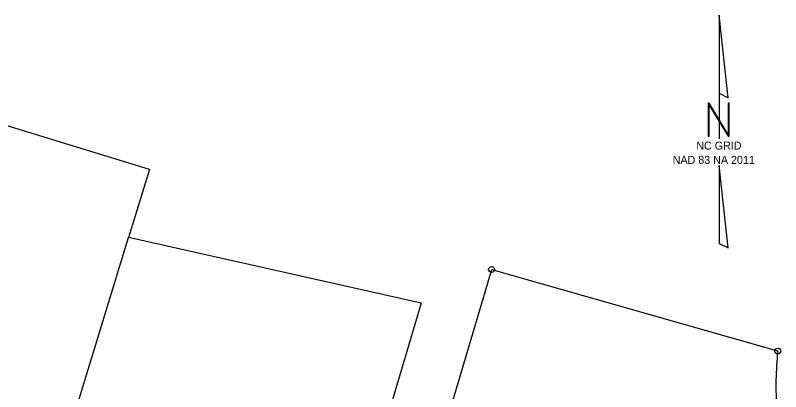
# Model space of a CAD drawing. Extents: x 2110969 to 2113691, y 670003 to 672285.
# Drawn here: x 2112129 to 2112703, y 670669 to 670951 of the extents above; entities that cross this region are included whole.
import ezdxf

# ---------------------------------------------------------------- set-up
doc = ezdxf.new("R2010")
doc.units = 0
for name, color, linetype in [('CTL North Arrow NAD 83 NA 2011 CELL', 7, 'Continuous'), ('Exist Property Iron Pin CELL', 7, 'Continuous'), ('Exist Property Line', 7, 'Continuous'), ('Exist Right of Way Line', 7, 'Continuous')]:
    doc.layers.add(name, color=color, linetype=linetype)

msp = doc.modelspace()

# ---------------------------------------------------------------- linework, layer by layer
at = {"layer": 'CTL North Arrow NAD 83 NA 2011 CELL'}
msp.add_line((2112657.28, 670863.37), (2112657.28, 670863.37), dxfattribs=at)
for points in [[(2112657.13, 670950.66), (2112657.13, 670892.33), (2112664, 670888.89)], [(2112648.9, 670860.11), (2112649.59, 670860.11), (2112649.59, 670883.43), (2112664, 670860.11), (2112664.69, 670860.11), (2112664.69, 670884.79), (2112664, 670884.79), (2112664, 670861.47), (2112649.59, 670884.79), (2112648.9, 670884.79)], [(2112657.13, 670779.82), (2112664, 670776.41), (2112657.13, 670838.14)]]:
    msp.add_lwpolyline(points, close=True, dxfattribs=at)
msp.add_lwpolyline([(2112657.13, 670892.33), (2112657.13, 670858.03)], dxfattribs=at)
at = {"layer": 'Exist Property Iron Pin CELL'}
for centre, radius in [((2112486.53, 670760.25), 2.2), ((2112486.53, 670760.25), 0.0707), ((2112701.1, 670699.11), 2.2), ((2112701.1, 670699.11), 0.0707)]:
    msp.add_circle(centre, radius, dxfattribs=at)
at = {"layer": 'Exist Property Line'}
for p, q in [((2112230.03, 670835.05), (2112062.75, 670886.44)), ((2112230.03, 670835.05), (2112214.4, 670784.17)), ((2112134.75, 670524.83), (2112214.4, 670784.17)), ((2112433.78, 670735.06), (2112214.4, 670784.17)), ((2112486.67, 670760.31), (2112701.03, 670699.23))]:
    msp.add_line(p, q, dxfattribs=at)
at = {"layer": 'Exist Right of Way Line'}
for p, q in [((2112434.29, 670583.29), (2112486.67, 670760.31)), ((2112433.78, 670735.06), (2112376.09, 670540.39))]:
    msp.add_line(p, q, dxfattribs=at)
msp.add_arc((2112974.74, 670672.66), 275, 174.45591, 183.61632, dxfattribs=at)

# ---------------------------------------------------------------- texts
at = {"layer": 'CTL North Arrow NAD 83 NA 2011 CELL'}
for s, p in [('NC GRID', (2112640.05, 670850.03)), ('NAD 83 NA 2011', (2112622.36, 670839.35))]:
    msp.add_text(s, height=6, dxfattribs=at).set_placement(p)

doc.saveas('drawing.dxf')
